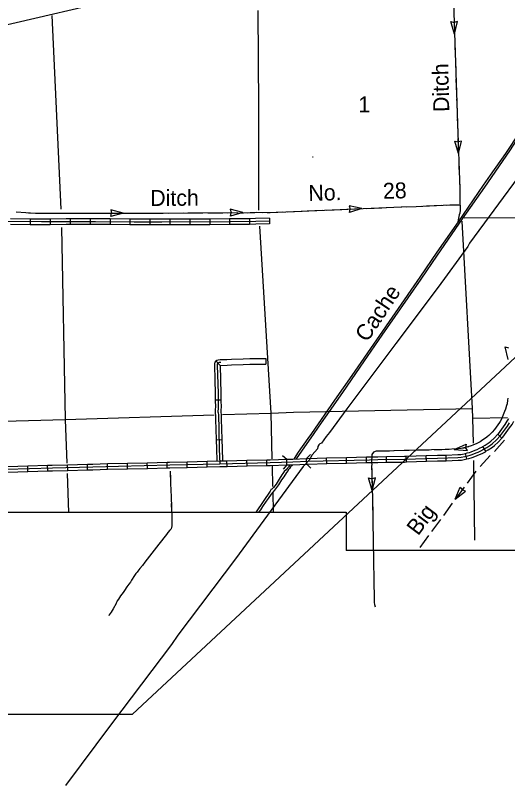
# Model space of a CAD drawing. Extents: x -5566 to 1759129, y -3726 to 731467.
# Drawn here: x -4979.9 to -4880.9, y 113.2 to 268.1 of the extents above; entities that cross this region are included whole.
import ezdxf

# ---------------------------------------------------------------- set-up
doc = ezdxf.new("R2010")
doc.units = 0
doc.layers.add('Default', color=7, linetype='Continuous')
doc.layers.add('R_No Plot', color=7, linetype='Continuous')

msp = doc.modelspace()

# ---------------------------------------------------------------- linework, layer by layer
at = {"layer": 'Default'}
for p, q in [((-5037.98, 253.01), (-4814.18, 305.51)), ((-4891.59, 264.36), (-4892.34, 266.85)), ((-4892.34, 266.85), (-4891.67, 266.69)), ((-4891, 266.89), (-4891.66, 266.69)), ((-4891.59, 264.36), (-4891, 266.89)), ((-4890.79, 240.31), (-4891.55, 242.8)), ((-4891.55, 242.8), (-4890.88, 242.65)), ((-4890.2, 242.85), (-4890.87, 242.65)), ((-4890.79, 240.31), (-4890.2, 242.85)), ((-4920.15, 239.64), (-4920.07, 239.66)), ((-4910.24, 229.26), (-4912.79, 229.83)), ((-4912.79, 229.83), (-4912.58, 229.17)), ((-4910.24, 229.26), (-4912.73, 228.48)), ((-4958.25, 228.33), (-4960.77, 229)), ((-4960.77, 229), (-4960.58, 228.33)), ((-4958.25, 228.33), (-4960.76, 227.65)), ((-4960.76, 227.65), (-4960.58, 228.33)), ((-4934.19, 228.46), (-4936.71, 229.12)), ((-4936.71, 229.12), (-4936.53, 228.45)), ((-4934.19, 228.46), (-4936.7, 227.77)), ((-4936.7, 227.77), (-4936.53, 228.44)), ((-4912.73, 228.48), (-4912.58, 229.16)), ((-4976.94, 227.15), (-4976.95, 226.02)), ((-4972.94, 227.15), (-4972.93, 226.02)), ((-4968.93, 227.18), (-4968.92, 226.04)), ((-4964.92, 227.2), (-4964.92, 226.06)), ((-4960.9, 227.17), (-4960.91, 226.03)), ((-4956.89, 227.12), (-4956.9, 225.98)), ((-4952.89, 227.12), (-4952.89, 225.98)), ((-4948.88, 227.13), (-4948.88, 225.99)), ((-4944.87, 227.14), (-4944.87, 226)), ((-4940.86, 227.15), (-4940.86, 226.01)), ((-4936.85, 227.17), (-4936.85, 226.03)), ((-4932.85, 227.22), (-4932.83, 226.08)), ((-4928.85, 227.31), (-4928.82, 226.17)), ((-4880.82, 198.92), (-4881.43, 201.46)), ((-4881.43, 201.46), (-4880.76, 201.26)), ((-4939.6, 198.66), (-4938.77, 197.74)), ((-4939.73, 190.82), (-4938.59, 190.83)), ((-4939.56, 182.8), (-4938.42, 182.83)), ((-4882.08, 183.09), (-4882.9, 183.88)), ((-4891.67, 180.81), (-4889.29, 181.88)), ((-4889.29, 181.88), (-4889.37, 181.21)), ((-4889.02, 180.6), (-4889.37, 181.2)), ((-4885.27, 180.46), (-4885.88, 181.42)), ((-4893.26, 178.57), (-4893.29, 179.71)), ((-4891.67, 180.81), (-4889.02, 180.6)), ((-4889.15, 178.92), (-4889.42, 180.02)), ((-4953.38, 177.03), (-4953.41, 178.17)), ((-4949.38, 177.13), (-4949.4, 178.27)), ((-4945.37, 177.23), (-4945.4, 178.37)), ((-4941.36, 177.33), (-4941.39, 178.47)), ((-4937.35, 177.43), (-4937.38, 178.57)), ((-4933.34, 177.52), (-4933.37, 178.66)), ((-4929.33, 177.61), (-4929.36, 178.74)), ((-4925.32, 177.72), (-4925.36, 178.86)), ((-4921.31, 177.88), (-4921.36, 179.02)), ((-4917.31, 177.98), (-4917.34, 179.12)), ((-4913.3, 178.08), (-4913.33, 179.22)), ((-4909.29, 178.18), (-4909.32, 179.32)), ((-4905.29, 178.25), (-4905.31, 179.39)), ((-4901.27, 178.32), (-4901.31, 179.46)), ((-4897.26, 178.45), (-4897.3, 179.59)), ((-4977.43, 176.4), (-4977.46, 177.54)), ((-4973.42, 176.51), (-4973.46, 177.65)), ((-4969.42, 176.62), (-4969.45, 177.76)), ((-4965.41, 176.73), (-4965.44, 177.87)), ((-4961.4, 176.84), (-4961.43, 177.98)), ((-4957.39, 176.93), (-4957.42, 178.07)), ((-4908.14, 172.61), (-4908.88, 175.11)), ((-4908.88, 175.11), (-4908.21, 174.94)), ((-4907.53, 175.14), (-4908.2, 174.95)), ((-4908.14, 172.61), (-4907.53, 175.14)), ((-4891.44, 170.81), (-4890.49, 173.24)), ((-4891.44, 170.81), (-4889.4, 172.43)), ((-4890.49, 173.24), (-4890.06, 172.69)), ((-4889.4, 172.43), (-4890.05, 172.69)), ((-5113.79, 127.64), (-4956.37, 127.64))]:
    msp.add_line(p, q, dxfattribs=at)
for points in [[(-4891.79, 270.71), (-4891.16, 250.51), (-4891, 246.34)], [(-4972.63, 268.1), (-4970.79, 229.12)], [(-4930.95, 228.97), (-4930.97, 249.59), (-4931.1, 269.1)], [(-4891.69, 267.36), (-4891.59, 264.36)], [(-4956.37, 127.64), (-4956.37, 127.64), (-4810.33, 263.68)], [(-4891.56, 263.35), (-4891.51, 261.85)], [(-4891.51, 261.85), (-4891.47, 260.35)], [(-4891.43, 259.35), (-4891.34, 256.34)], [(-4891.31, 255.34), (-4891.22, 252.33)], [(-4891.18, 251.33), (-4891.16, 250.51), (-4891.08, 248.33)], [(-4876.4, 247.4), (-4877.86, 245.4), (-4878.09, 245.14), (-4878.34, 244.83), (-4878.58, 244.5), (-4881.37, 240.35), (-4884.41, 235.99), (-4885.86, 233.97), (-4890.88, 226.63), (-4895.17, 220.49), (-4898.6, 215.46), (-4912.27, 195.73), (-4915.76, 190.72), (-4920.35, 184.07), (-4921.09, 183.01), (-4923.05, 180.27), (-4923.53, 179.57), (-4923.92, 178.9)], [(-4875.8, 247.76), (-4876.46, 246.77), (-4877.29, 245.56), (-4877.64, 245.15), (-4878.17, 244.42), (-4878.72, 243.65), (-4879.18, 242.93), (-4880.54, 240.9), (-4885.6, 233.57), (-4890.03, 227.2), (-4895.07, 219.92), (-4898.37, 215.07), (-4906.21, 203.79), (-4910.67, 197.39), (-4914.14, 192.31), (-4916.83, 188.47), (-4918.42, 186.18), (-4919.9, 184.01), (-4922.4, 180.5), (-4923.48, 178.92)], [(-4891.04, 247.32), (-4891, 246.34), (-4890.93, 244.32)], [(-4891, 246.34), (-4890.54, 233.12), (-4890.5, 230.29), (-4890.47, 229.73), (-4890.46, 228.94), (-4890.51, 228.36), (-4890.64, 228.01), (-4890.73, 227.65), (-4890.9, 226.61)], [(-4872.96, 243.47), (-4888.59, 222.29), (-4888.9, 221.63), (-4894.9, 213.43), (-4903.43, 202.16), (-4913.29, 189.03), (-4916.78, 184.22), (-4917.39, 183.46), (-4918.39, 182.12), (-4918.72, 181.98), (-4918.91, 181.74), (-4919.08, 181.4), (-4919.19, 180.97), (-4920.21, 179.74), (-4920.86, 178.7), (-4922.02, 177.38), (-4935.68, 158.87), (-4947.25, 143.46), (-4948.57, 141.64), (-4960.58, 125.69), (-4969.88, 113.25)], [(-4890.9, 243.32), (-4890.79, 240.31)], [(-4890.76, 239.31), (-4890.7, 237.81)], [(-4890.7, 237.81), (-4890.65, 236.3)], [(-4890.62, 235.3), (-4890.54, 233.12), (-4890.53, 232.3)], [(-4890.51, 231.29), (-4890.5, 230.29), (-4890.47, 229.73), (-4890.46, 228.94), (-4890.51, 228.36), (-4890.54, 228.29)], [(-4935.34, 228.36), (-4931.45, 228.51), (-4928.66, 228.5), (-4906.86, 229.4), (-4902.33, 229.61), (-4899.3, 229.7), (-4892.51, 230.01), (-4890.73, 230), (-4890.48, 229.93)], [(-4913.25, 229.14), (-4910.24, 229.26)], [(-4909.24, 229.3), (-4907.74, 229.36)], [(-4907.74, 229.36), (-4906.86, 229.4), (-4906.24, 229.43)], [(-4905.24, 229.48), (-4902.33, 229.61), (-4902.23, 229.62)], [(-4901.23, 229.64), (-4899.3, 229.7), (-4898.23, 229.75)], [(-4897.22, 229.8), (-4894.22, 229.93)], [(-4893.22, 229.98), (-4892.51, 230.01), (-4890.73, 230), (-4890.48, 229.93)], [(-4979.79, 228.62), (-4975.87, 228.33), (-4971.89, 228.31), (-4950.53, 228.35), (-4935.34, 228.46)], [(-4977.29, 228.43), (-4975.87, 228.33), (-4974.29, 228.32)], [(-4973.28, 228.31), (-4971.89, 228.31), (-4970.28, 228.31)], [(-4969.27, 228.31), (-4966.27, 228.32)], [(-4965.26, 228.32), (-4962.26, 228.33)], [(-4961.25, 228.33), (-4958.25, 228.33)], [(-4957.24, 228.34), (-4955.74, 228.34)], [(-4955.74, 228.34), (-4954.24, 228.34)], [(-4953.23, 228.35), (-4950.53, 228.35), (-4950.23, 228.35)], [(-4949.22, 228.36), (-4946.22, 228.38)], [(-4945.22, 228.39), (-4942.21, 228.41)], [(-4941.21, 228.42), (-4938.2, 228.44)], [(-4937.2, 228.44), (-4935.34, 228.46), (-4935.34, 228.36), (-4934.29, 228.4)], [(-4933.28, 228.44), (-4931.78, 228.5)], [(-4931.78, 228.5), (-4931.45, 228.51), (-4930.28, 228.5)], [(-4929.28, 228.5), (-4928.66, 228.5), (-4926.27, 228.6)], [(-4925.27, 228.64), (-4922.26, 228.76)], [(-4921.26, 228.8), (-4918.26, 228.93)], [(-4917.26, 228.97), (-4914.25, 229.09)], [(-4928.83, 226.74), (-4931.6, 226.67), (-4936.66, 226.6), (-4950.46, 226.55), (-4956.03, 226.54), (-4963.81, 226.63), (-4969.75, 226.61), (-4974.72, 226.57), (-4991.09, 226.67)], [(-4976.94, 227.15), (-4980.95, 227.18)], [(-4972.94, 227.15), (-4974.72, 227.14), (-4976.94, 227.15)], [(-4968.93, 227.18), (-4969.76, 227.18), (-4972.94, 227.15)], [(-4964.92, 227.2), (-4968.93, 227.18)], [(-4960.9, 227.17), (-4963.8, 227.2), (-4964.92, 227.2)], [(-4956.89, 227.12), (-4960.9, 227.17)], [(-4952.89, 227.12), (-4956.03, 227.11), (-4956.89, 227.12)], [(-4948.88, 227.13), (-4950.46, 227.12), (-4952.89, 227.12)], [(-4944.87, 227.14), (-4948.88, 227.13)], [(-4940.86, 227.15), (-4944.87, 227.14)], [(-4936.85, 227.17), (-4940.86, 227.15)], [(-4932.85, 227.22), (-4936.66, 227.17), (-4936.85, 227.17)], [(-4928.85, 227.31), (-4931.61, 227.24), (-4932.85, 227.22)], [(-4928.82, 226.17), (-4931.59, 226.1), (-4932.83, 226.08)], [(-4890.78, 227.33), (-4890.9, 226.61)], [(-4890.11, 226.73), (-4888.05, 189.1), (-4887.95, 187.15), (-4887.87, 182.12)], [(-4847.62, 227.58), (-4889.68, 227.36)], [(-4976.95, 226.02), (-4980.96, 226.04)], [(-4972.93, 226.02), (-4974.72, 226), (-4976.95, 226.02)], [(-4968.92, 226.04), (-4969.75, 226.04), (-4972.93, 226.02)], [(-4970.69, 225.47), (-4969.95, 186.87)], [(-4964.92, 226.06), (-4968.92, 226.04)], [(-4960.91, 226.03), (-4963.81, 226.06), (-4964.92, 226.06)], [(-4956.9, 225.98), (-4960.91, 226.03)], [(-4952.89, 225.98), (-4956.03, 225.97), (-4956.9, 225.98)], [(-4948.88, 225.99), (-4950.46, 225.98), (-4952.89, 225.98)], [(-4944.87, 226), (-4948.88, 225.99)], [(-4940.86, 226.01), (-4944.87, 226)], [(-4936.85, 226.03), (-4940.86, 226.01)], [(-4932.83, 226.08), (-4936.65, 226.03), (-4936.85, 226.03)], [(-4928.52, 188.15), (-4930.78, 225.71)], [(-4939.6, 198.66), (-4939.82, 198.39), (-4939.9, 198.05), (-4939.91, 197.76), (-4939.82, 194.82)], [(-4939.6, 198.66), (-4939.41, 198.78), (-4939.17, 198.86), (-4938.74, 198.91), (-4937.39, 198.93), (-4936.49, 198.98), (-4934.14, 199.07), (-4932.77, 199.1), (-4929.58, 199.14), (-4929.57, 198)], [(-4938.64, 198.31), (-4938.97, 198.31), (-4939.1, 198.28), (-4939.23, 198.21), (-4939.3, 198.13), (-4939.33, 197.97), (-4939.34, 197.77), (-4939.17, 192.08), (-4939.15, 189.24), (-4939.18, 188.95), (-4939.2, 188.63), (-4939.21, 188.41), (-4939.17, 188.19), (-4939.11, 187.79), (-4939.05, 184.94), (-4938.93, 180.98), (-4938.8, 177.97)], [(-4938.77, 197.74), (-4937.33, 197.79), (-4936.44, 197.84), (-4934.11, 197.93), (-4932.75, 197.96), (-4929.57, 198)], [(-4938.77, 197.74), (-4938.68, 194.85)], [(-4939.82, 194.82), (-4939.74, 192.07), (-4939.73, 190.82)], [(-4938.68, 194.85), (-4938.6, 192.09), (-4938.59, 190.83)], [(-4939.73, 190.82), (-4939.72, 189.27), (-4939.75, 188.99), (-4939.77, 188.66), (-4939.78, 188.38), (-4939.73, 188.1), (-4939.67, 187.73), (-4939.66, 186.81)], [(-4938.59, 190.83), (-4938.58, 189.22), (-4938.61, 188.91), (-4938.63, 188.61), (-4938.63, 188.45), (-4938.61, 188.28), (-4938.54, 187.84), (-4938.52, 186.84)], [(-4880.86, 191.12), (-4880.95, 190.77), (-4881.04, 190.03), (-4881.14, 189.64), (-4881.34, 188.96), (-4881.55, 188.48), (-4881.79, 187.8), (-4882.01, 187.23), (-4882.13, 186.93), (-4882.4, 186.47), (-4882.86, 185.8), (-4883.56, 184.84), (-4884, 184.31), (-4884.68, 183.62), (-4885.38, 183.07), (-4885.89, 182.77), (-4886.43, 182.39), (-4887.26, 181.96), (-4888.22, 181.56), (-4888.89, 181.34), (-4889.71, 181.11), (-4890.29, 181.03), (-4890.85, 180.94), (-4893.47, 180.8), (-4901.72, 180.6), (-4903.78, 180.54), (-4905.58, 180.49), (-4906.62, 180.47), (-4906.8, 180.48), (-4907.39, 180.46), (-4907.91, 180.29), (-4908.24, 179.85), (-4908.27, 178.14)], [(-4928.52, 188.15), (-4923.99, 188.33), (-4888.05, 189.1)], [(-4881.07, 189.93), (-4881.14, 189.64), (-4881.34, 188.96), (-4881.55, 188.48), (-4881.79, 187.8), (-4882.01, 187.23), (-4882.06, 187.1)], [(-4969.95, 186.87), (-4939.95, 187.79)], [(-4938.27, 187.85), (-4928.52, 188.15)], [(-4928.27, 178.96), (-4928.52, 188.15)], [(-5008.59, 185.91), (-4999.48, 186.07), (-4969.95, 186.87)], [(-4969.95, 186.87), (-4969.61, 178.06)], [(-4939.66, 186.81), (-4939.62, 184.93), (-4939.56, 182.8)], [(-4938.52, 186.84), (-4938.48, 184.96), (-4938.42, 182.83)], [(-4928.67, 178.19), (-4924.14, 178.33), (-4921.1, 178.46), (-4908.71, 178.76), (-4907.02, 178.79), (-4901.65, 178.88), (-4895.03, 179.09), (-4890.92, 179.22), (-4890.29, 179.27), (-4889.53, 179.41), (-4888.89, 179.57), (-4888.43, 179.7), (-4888.03, 179.84), (-4887.24, 180.13), (-4886.82, 180.32), (-4886.3, 180.54), (-4885.69, 180.87), (-4885.12, 181.23), (-4884.31, 181.78), (-4883.95, 182.06), (-4883.22, 182.72), (-4882.35, 183.63), (-4880.97, 185.54), (-4880.51, 186.19)], [(-4887.95, 187.15), (-4880.93, 187.27)], [(-4882.57, 186.23), (-4882.86, 185.8), (-4883.56, 184.84), (-4884, 184.31), (-4884.42, 183.88)], [(-4882.9, 183.88), (-4882.78, 184), (-4881.44, 185.87), (-4880.99, 186.5), (-4880.74, 186.93), (-4880.68, 187.03)], [(-4882.08, 183.09), (-4881.91, 183.27), (-4880.51, 185.21), (-4880.03, 185.88), (-4879.75, 186.36), (-4879.69, 186.48)], [(-4939.56, 182.8), (-4939.5, 180.95), (-4939.4, 178.52)], [(-4938.42, 182.83), (-4938.37, 181), (-4938.26, 178.55)], [(-4885.18, 183.22), (-4885.38, 183.07), (-4885.89, 182.77), (-4886.43, 182.39), (-4887.26, 181.96), (-4887.79, 181.74)], [(-4885.88, 181.42), (-4885.43, 181.71), (-4884.65, 182.24), (-4884.32, 182.5), (-4883.62, 183.13), (-4882.9, 183.88)], [(-4885.27, 180.46), (-4884.8, 180.75), (-4883.98, 181.32), (-4883.59, 181.62), (-4882.82, 182.31), (-4882.08, 183.09)], [(-4888.73, 181.39), (-4888.89, 181.34), (-4890.29, 181.03), (-4890.85, 180.94), (-4891.67, 180.81)], [(-4889.42, 180.02), (-4889.04, 180.12), (-4888.6, 180.25), (-4888.22, 180.38), (-4887.45, 180.66), (-4887.05, 180.84), (-4886.55, 181.06), (-4885.97, 181.36), (-4885.88, 181.42)], [(-4881.56, 182.68), (-4883.57, 180.45)], [(-4926.18, 179.64), (-4925.36, 178.86)], [(-4921.35, 179.02), (-4920.58, 179.85)], [(-4904.7, 180.51), (-4905.58, 180.49), (-4906.62, 180.47), (-4906.8, 180.48), (-4907.39, 180.46), (-4907.7, 180.36)], [(-4900.7, 180.62), (-4901.72, 180.6), (-4903.7, 180.54)], [(-4896.69, 180.72), (-4899.69, 180.65)], [(-4897.3, 179.59), (-4895.04, 179.66), (-4893.29, 179.71)], [(-4894.18, 180.78), (-4895.69, 180.75)], [(-4892.68, 180.84), (-4893.47, 180.8), (-4894.18, 180.78)], [(-4893.29, 179.71), (-4890.95, 179.79), (-4890.36, 179.84), (-4889.65, 179.96), (-4889.42, 180.02)], [(-4889.15, 178.92), (-4888.74, 179.02), (-4888.26, 179.16), (-4887.84, 179.3), (-4887.02, 179.6), (-4886.59, 179.8), (-4886.05, 180.03), (-4885.4, 180.38), (-4885.27, 180.46)], [(-4884.46, 179.65), (-4886.44, 177.39)], [(-5009.52, 176.17), (-5006.29, 176.21), (-4990.96, 176.61), (-4986.41, 176.72), (-4972.5, 177.11), (-4964.36, 177.33), (-4948.9, 177.71), (-4938.8, 177.97), (-4928.67, 178.19)], [(-4957.42, 178.07), (-4953.41, 178.17)], [(-4953.41, 178.17), (-4949.4, 178.27)], [(-4949.4, 178.27), (-4948.91, 178.28), (-4945.4, 178.37)], [(-4945.4, 178.37), (-4941.39, 178.47)], [(-4941.39, 178.47), (-4938.82, 178.54), (-4937.38, 178.57)], [(-4937.38, 178.57), (-4933.37, 178.66)], [(-4933.37, 178.66), (-4929.36, 178.74)], [(-4929.36, 178.74), (-4928.68, 178.76), (-4925.36, 178.86)], [(-4925.36, 178.86), (-4924.16, 178.89), (-4921.36, 179.02)], [(-4921.36, 179.02), (-4921.12, 179.03), (-4917.34, 179.12)], [(-4917.34, 179.12), (-4913.33, 179.22)], [(-4913.33, 179.22), (-4909.32, 179.32)], [(-4913.3, 178.08), (-4909.29, 178.18)], [(-4909.32, 179.32), (-4908.73, 179.33), (-4907.03, 179.36), (-4905.31, 179.39)], [(-4909.29, 178.18), (-4908.7, 178.19), (-4907.01, 178.22), (-4905.29, 178.25)], [(-4908.27, 178.2), (-4908.26, 177.81), (-4908.27, 177.49), (-4908.25, 176.62)], [(-4908.27, 178.14), (-4908.26, 177.81), (-4908.27, 177.49), (-4908.23, 175.89), (-4908.09, 170.7), (-4907.98, 162.29), (-4907.79, 150.74), (-4907.76, 150.04), (-4907.68, 149.69), (-4907.58, 149.21)], [(-4908.24, 179.62), (-4908.25, 179.34)], [(-4905.31, 179.39), (-4901.67, 179.45), (-4901.31, 179.46)], [(-4905.29, 178.25), (-4901.64, 178.31), (-4901.27, 178.32)], [(-4901.31, 179.46), (-4897.3, 179.59)], [(-4901.27, 178.32), (-4897.26, 178.45)], [(-4897.26, 178.45), (-4895.01, 178.52), (-4893.26, 178.57)], [(-4893.26, 178.57), (-4890.89, 178.65), (-4890.21, 178.71), (-4889.41, 178.85), (-4889.15, 178.92)], [(-4887.81, 178.6), (-4887.56, 162.62)], [(-4981.47, 177.43), (-4977.46, 177.54)], [(-4977.46, 177.54), (-4973.46, 177.65)], [(-4973.46, 177.65), (-4972.52, 177.68), (-4969.45, 177.76)], [(-4973.42, 176.51), (-4972.48, 176.54), (-4969.42, 176.62)], [(-4969.45, 177.76), (-4965.44, 177.87)], [(-4969.42, 176.62), (-4965.41, 176.73)], [(-4965.44, 177.87), (-4964.37, 177.9), (-4961.43, 177.98)], [(-4965.41, 176.73), (-4964.34, 176.76), (-4961.4, 176.84)], [(-4961.43, 177.98), (-4957.42, 178.07)], [(-4961.4, 176.84), (-4957.39, 176.93)], [(-4957.39, 176.93), (-4953.38, 177.03)], [(-4953.38, 177.03), (-4949.38, 177.13)], [(-4949.38, 177.13), (-4948.88, 177.14), (-4945.37, 177.23)], [(-4945.37, 177.23), (-4941.36, 177.33)], [(-4941.36, 177.33), (-4938.79, 177.4), (-4937.35, 177.43)], [(-4937.35, 177.43), (-4933.34, 177.52)], [(-4933.34, 177.52), (-4929.33, 177.61)], [(-4924.74, 177.74), (-4925.03, 177.27), (-4925.29, 177.02), (-4925.5, 176.74), (-4925.84, 176.38), (-4926.14, 175.98), (-4926.36, 175.7), (-4926.85, 174.86), (-4927.49, 173.85), (-4928.05, 173.19), (-4928.35, 172.87), (-4928.54, 172.75), (-4928.57, 172.73), (-4928.69, 172.42), (-4931.49, 168.3)], [(-4924.26, 177.75), (-4924.37, 177.52), (-4924.57, 177.32), (-4924.83, 177.03), (-4925, 176.8), (-4925.1, 176.6), (-4925.4, 176.21), (-4925.97, 175.36), (-4926.42, 174.72), (-4927.01, 173.75), (-4927.84, 172.64), (-4928.47, 171.83), (-4929.06, 170.98), (-4929.47, 170.42), (-4930.2, 169.35), (-4930.65, 168.69), (-4930.95, 168.26)], [(-4929.33, 177.61), (-4928.65, 177.62), (-4925.32, 177.72)], [(-4928.12, 173.37), (-4928.24, 177.55)], [(-4925.32, 177.72), (-4926.1, 176.89)], [(-4925.32, 177.72), (-4924.12, 177.76), (-4921.31, 177.88)], [(-4921.31, 177.88), (-4921.09, 177.89), (-4917.31, 177.98)], [(-4920.48, 177.1), (-4921.31, 177.88)], [(-4917.31, 177.98), (-4913.3, 178.08)], [(-4981.44, 176.29), (-4977.43, 176.4)], [(-4977.43, 176.4), (-4973.42, 176.51)], [(-4969.53, 176.01), (-4969.23, 168.18)], [(-4948.84, 176.5), (-4948.73, 174), (-4948.63, 171.31), (-4948.5, 167.09), (-4948.46, 165.8), (-4948.46, 165.45), (-4948.54, 165.11), (-4948.6, 164.9), (-4948.88, 164.58), (-4949.29, 164.12), (-4949.39, 163.94), (-4949.55, 163.73), (-4951.07, 161.81), (-4953.91, 158.2), (-4954.39, 157.52), (-4954.89, 156.91), (-4955.1, 156.61), (-4955.29, 156.37), (-4955.46, 156.18), (-4955.72, 155.86), (-4955.98, 155.47), (-4956.58, 154.57), (-4956.78, 154.16), (-4957.09, 153.72), (-4957.55, 153.18), (-4957.98, 152.45), (-4958.29, 152.04), (-4958.78, 151.37), (-4959.21, 150.73), (-4959.44, 150.39), (-4959.56, 150.18), (-4959.7, 149.92), (-4959.7, 149.88), (-4960.29, 148.81), (-4960.7, 148.12), (-4961.07, 147.55), (-4961.12, 147.41)], [(-4948.84, 176.5), (-4948.77, 175)], [(-4908.22, 175.61), (-4908.14, 172.61)], [(-4887.28, 176.46), (-4889.06, 174.04)], [(-4948.73, 174), (-4948.63, 171.31), (-4948.62, 170.99)], [(-4927.99, 168.26), (-4928.09, 172.18)], [(-4890.55, 172.02), (-4891.44, 170.81)], [(-4889.66, 173.23), (-4890.55, 172.02)], [(-4908.11, 171.61), (-4908.09, 170.7), (-4908.08, 170.1)], [(-4948.58, 169.99), (-4948.53, 168.43), (-4948.52, 168.33)], [(-4908.08, 170.1), (-4908.06, 168.6)], [(-4892.04, 170), (-4893.82, 167.58)], [(-4908.05, 167.6), (-4908.01, 164.59)], [(-4894.42, 166.78), (-4896.01, 164.62), (-4896.21, 164.36)], [(-4907.99, 163.59), (-4907.98, 162.29), (-4907.95, 160.58)], [(-4896.81, 163.56), (-4898.61, 161.15)]]:
    msp.add_lwpolyline(points, dxfattribs=at)
at = {"layer": 'R_No Plot'}
for points in [[(-5018.99, 168.24), (-5018.99, 511.98), (-4446.6, 511.98), (-4446.6, 160.5), (-4913.43, 160.5)], [(-5018.99, 168.24), (-4913.43, 168.24), (-4913.43, 160.5)]]:
    msp.add_lwpolyline(points, dxfattribs=at)

# ---------------------------------------------------------------- texts
at = {"layer": 'Default'}
for s, height, rotation, p in [('Ditch', 3.205, 91.3019, (-4892.65, 248.72)), ('No.       28', 3.2048, 1.6678, (-4920.95, 230.78)), ('Ditch', 3.205, 0.2855, (-4952.81, 229.79)), ('Cache', 3.205, 56.2833, (-4909.17, 202.24)), ('Big', 3.205, 53.1448, (-4898.93, 163.34))]:
    msp.add_text(s, height=height, rotation=rotation, dxfattribs=at).set_placement(p)
msp.add_text('1', height=3.2, dxfattribs=at).set_placement((-4910.93, 248.63))

doc.saveas('drawing.dxf')
